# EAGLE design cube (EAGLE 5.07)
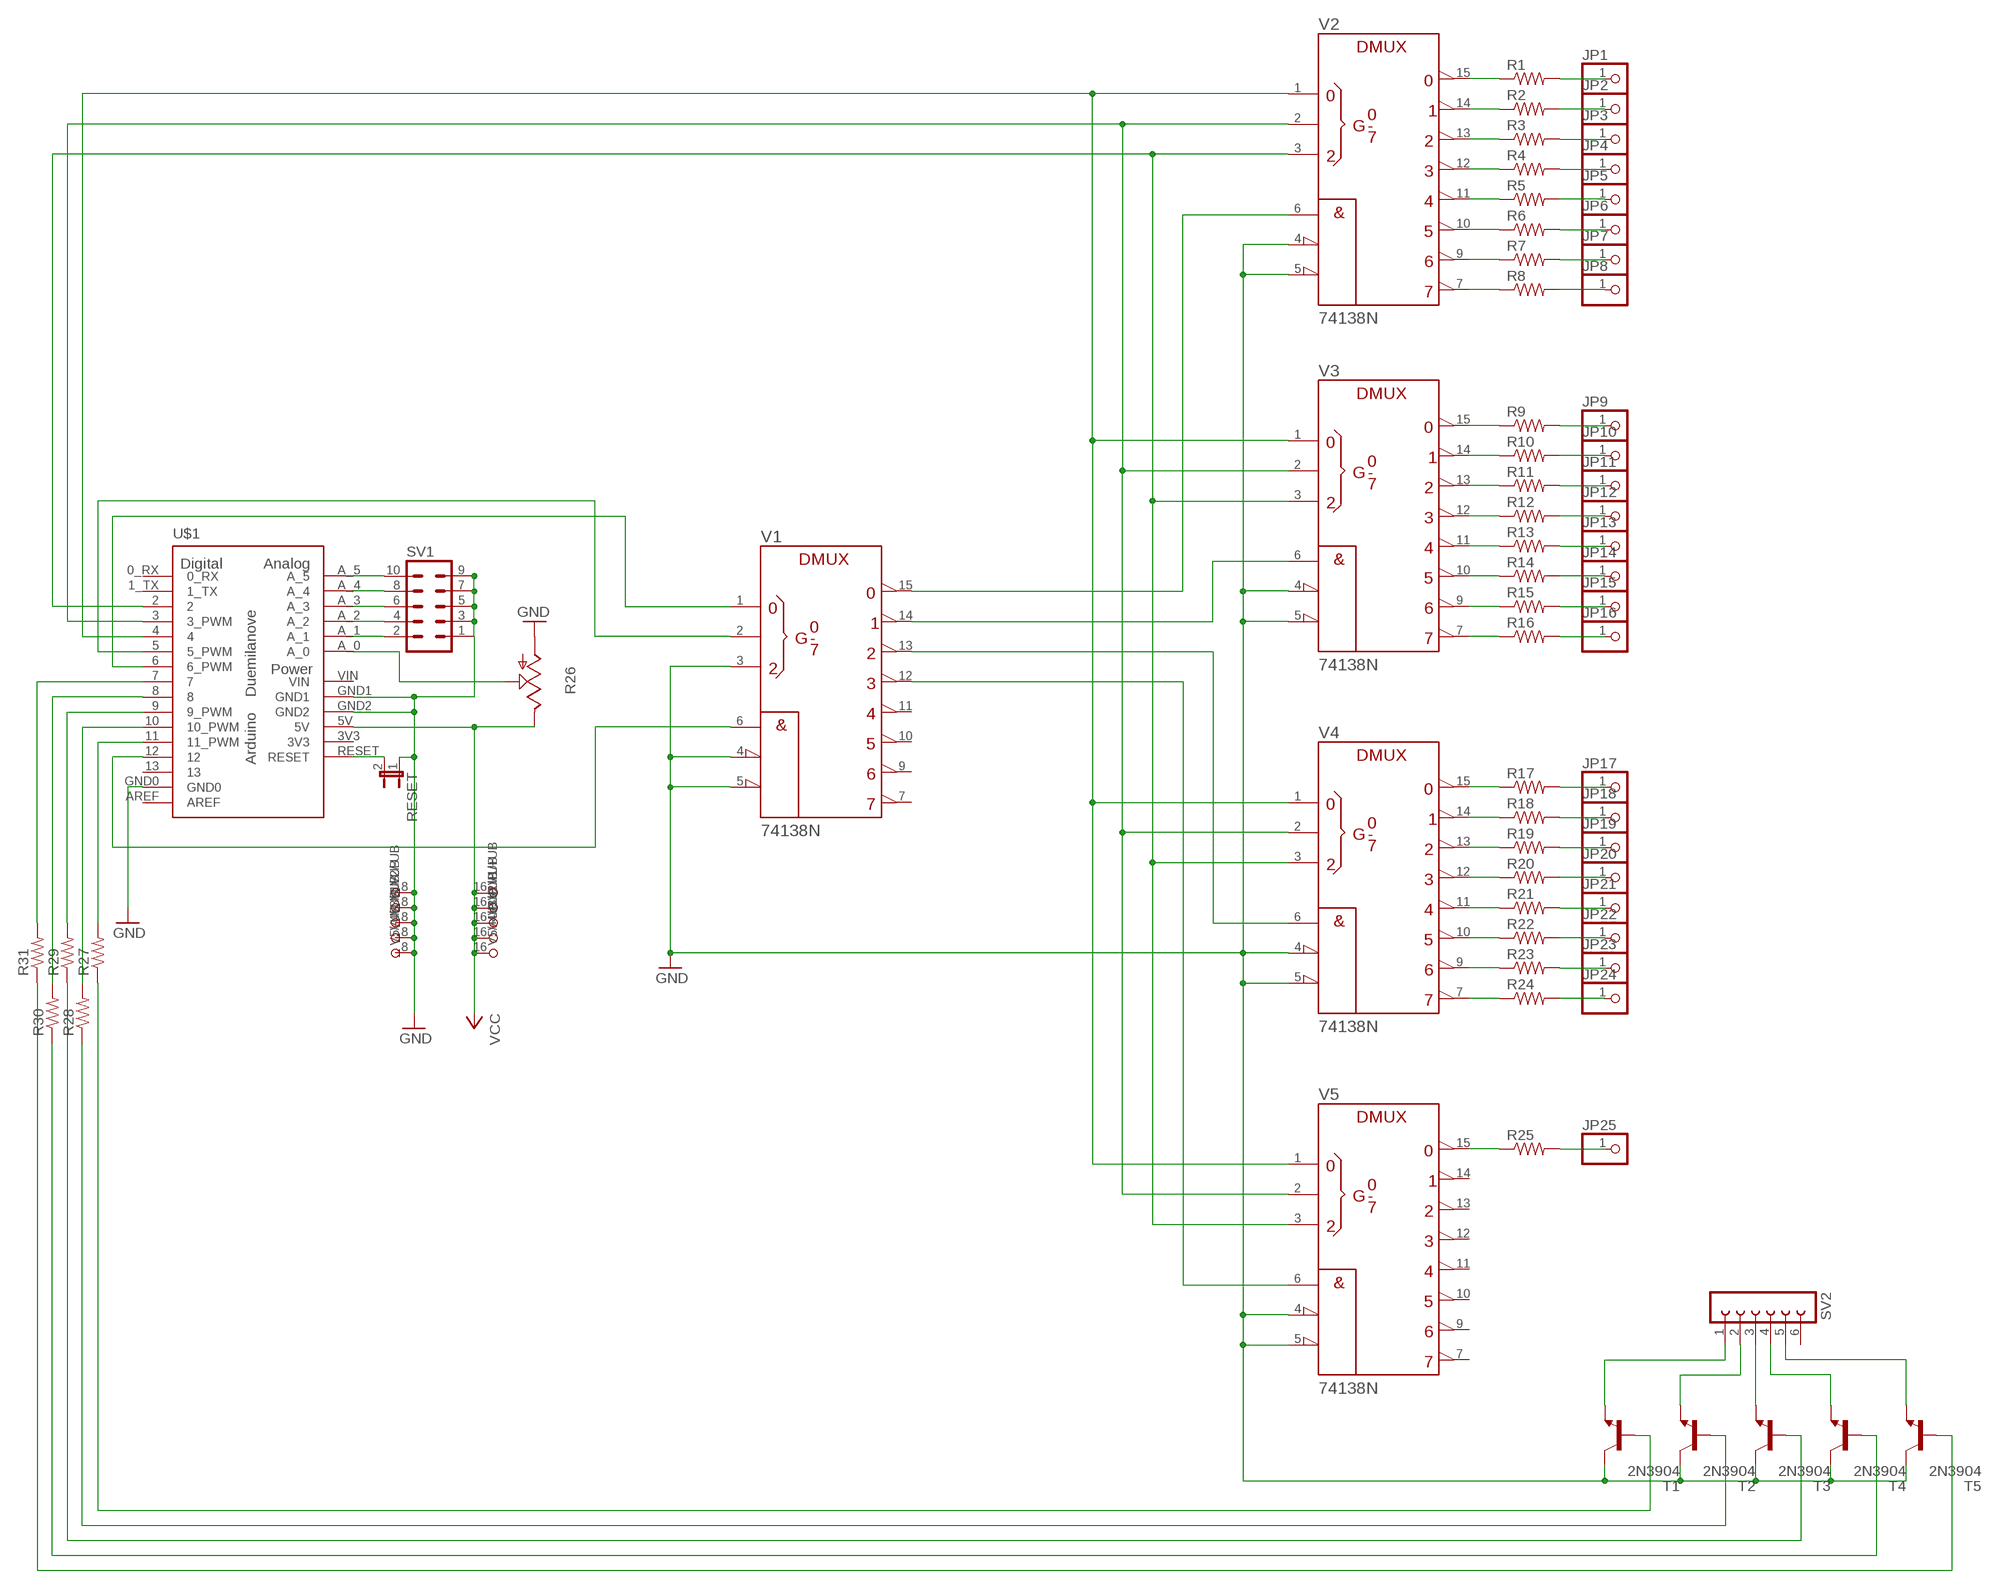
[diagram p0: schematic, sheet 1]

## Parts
JP1  PINHD-1X1  [1X01]
JP2  PINHD-1X1  [1X01]
JP3  PINHD-1X1  [1X01]
JP4  PINHD-1X1  [1X01]
JP5  PINHD-1X1  [1X01]
JP6  PINHD-1X1  [1X01]
JP7  PINHD-1X1  [1X01]
JP8  PINHD-1X1  [1X01]
JP9  PINHD-1X1  [1X01]
JP10  PINHD-1X1  [1X01]
JP11  PINHD-1X1  [1X01]
JP12  PINHD-1X1  [1X01]
JP13  PINHD-1X1  [1X01]
JP14  PINHD-1X1  [1X01]
JP15  PINHD-1X1  [1X01]
JP16  PINHD-1X1  [1X01]
JP17  PINHD-1X1  [1X01]
JP18  PINHD-1X1  [1X01]
JP19  PINHD-1X1  [1X01]
JP20  PINHD-1X1  [1X01]
JP21  PINHD-1X1  [1X01]
JP22  PINHD-1X1  [1X01]
JP23  PINHD-1X1  [1X01]
JP24  PINHD-1X1  [1X01]
JP25  PINHD-1X1  [1X01]
R1  R-US_0207/10  [0207/10]
R2  R-US_0207/10  [0207/10]
R3  R-US_0207/10  [0207/10]
R4  R-US_0207/10  [0207/10]
R5  R-US_0207/10  [0207/10]
R6  R-US_0207/10  [0207/10]
R7  R-US_0207/10  [0207/10]
R8  R-US_0207/10  [0207/10]
R9  R-US_0207/10  [0207/10]
R10  R-US_0207/10  [0207/10]
R11  R-US_0207/10  [0207/10]
R12  R-US_0207/10  [0207/10]
R13  R-US_0207/10  [0207/10]
R14  R-US_0207/10  [0207/10]
R15  R-US_0207/10  [0207/10]
R16  R-US_0207/10  [0207/10]
R17  R-US_0207/10  [0207/10]
R18  R-US_0207/10  [0207/10]
R19  R-US_0207/10  [0207/10]
R20  R-US_0207/10  [0207/10]
R21  R-US_0207/10  [0207/10]
R22  R-US_0207/10  [0207/10]
R23  R-US_0207/10  [0207/10]
R24  R-US_0207/10  [0207/10]
R25  R-US_0207/10  [0207/10]
R26  TRIM_US-CA6V  [CA6V]
R27  R-US_0207/10  [0207/10]
R28  R-US_0207/10  [0207/10]
R29  R-US_0207/10  [0207/10]
R30  R-US_0207/10  [0207/10]
R31  R-US_0207/10  [0207/10]
RESET  JP1E  [JP1]
SV1  MA05-2  [MA05-2]
SV2  FE06-1  [FE06]
T1  2N3904  [TO92]
T2  2N3904  [TO92]
T3  2N3904  [TO92]
T4  2N3904  [TO92]
T5  2N3904  [TO92]
U$1  ARDUINO-USBOCTAGONAL_PADS  [SHIELD-OCTAGONALPAD]
V1  74138N  [DIL16]
V2  74138N  [DIL16]
V3  74138N  [DIL16]
V4  74138N  [DIL16]
V5  74138N  [DIL16]

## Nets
GND: R26.A RESET.1 SV1.1 SV1.3 SV1.5 SV1.7 SV1.9 T1.1(C) T2.1(C) T3.1(C) T4.1(C) T5.1(C) U$1.GND0 U$1.GND1 U$1.GND2 V1.3(C) V1.4(!G2A) V1.5(!G2B) V1.8(-UB) V2.4(!G2A) V2.5(!G2B) V2.8(-UB) V3.4(!G2A) V3.5(!G2B) V3.8(-UB) V4.4(!G2A) V4.5(!G2B) V4.8(-UB) V5.4(!G2A) V5.5(!G2B) V5.8(-UB)
N$1: U$1.6(6_PWM) V1.1(A)
N$2: U$1.12 V1.6(G1)
N$3: V1.15(Y0) V2.6(G1)
N$4: V1.14(Y1) V3.6(G1)
N$5: V1.13(Y2) V4.6(G1)
N$6: V1.12(Y3) V5.6(G1)
N$7: U$1.4 V2.1(A) V3.1(A) V4.1(A) V5.1(A)
N$8: U$1.3(3_PWM) V2.2(B) V3.2(B) V4.2(B) V5.2(B)
N$9: U$1.2 V2.3(C) V3.3(C) V4.3(C) V5.3(C)
N$10: R27.1 T1.2(B)
N$11: R28.1 T2.2(B)
N$12: R29.1 T3.2(B)
N$13: R30.1 T4.2(B)
N$14: R31.1 T5.2(B)
N$15: R1.1 V2.15(Y0)
N$16: R2.1 V2.14(Y1)
N$17: R3.1 V2.13(Y2)
N$18: R4.1 V2.12(Y3)
N$19: R5.1 V2.11(Y4)
N$20: R6.1 V2.10(Y5)
N$21: R7.1 V2.9(Y6)
N$22: R8.1 V2.7(Y7)
N$23: R9.1 V3.15(Y0)
N$24: R10.1 V3.14(Y1)
N$25: R11.1 V3.13(Y2)
N$26: R12.1 V3.12(Y3)
N$27: R13.1 V3.11(Y4)
N$28: R14.1 V3.10(Y5)
N$29: R15.1 V3.9(Y6)
N$30: R16.1 V3.7(Y7)
N$31: R17.1 V4.15(Y0)
N$32: R18.1 V4.14(Y1)
N$33: R19.1 V4.13(Y2)
N$34: R20.1 V4.12(Y3)
N$35: R21.1 V4.11(Y4)
N$36: R22.1 V4.10(Y5)
N$37: R23.1 V4.9(Y6)
N$38: R24.1 V4.7(Y7)
N$39: R25.1 V5.15(Y0)
N$40: JP1.1 R1.2
N$41: JP2.1 R2.2
N$42: JP3.1 R3.2
N$43: JP4.1 R4.2
N$44: JP5.1 R5.2
N$45: JP6.1 R6.2
N$46: JP7.1 R7.2
N$47: JP8.1 R8.2
N$48: JP9.1 R9.2
N$49: JP10.1 R10.2
N$50: JP11.1 R11.2
N$51: JP12.1 R12.2
N$52: JP13.1 R13.2
N$53: JP14.1 R14.2
N$54: JP15.1 R15.2
N$55: JP16.1 R16.2
N$56: JP17.1 R17.2
N$57: JP18.1 R18.2
N$58: JP19.1 R19.2
N$59: JP20.1 R20.2
N$60: JP21.1 R21.2
N$61: JP22.1 R22.2
N$62: JP23.1 R23.2
N$63: JP24.1 R24.2
N$64: JP25.1 R25.2
N$65: SV2.1 T1.3(E)
N$66: SV2.2 T2.3(E)
N$67: SV2.3 T3.3(E)
N$68: SV2.4 T4.3(E)
N$69: SV2.5 T5.3(E)
N$70: U$1.5(5_PWM) V1.2(B)
N$71: SV1.2 U$1.A_1
N$72: SV1.4 U$1.A_2
N$73: SV1.6 U$1.A_3
N$74: SV1.8 U$1.A_4
N$75: SV1.10 U$1.A_5
N$76: R26.S U$1.A_0
N$77: R27.2 U$1.11(11_PWM)
N$78: RESET.2 U$1.RESET
N$79: R28.2 U$1.10(10_PWM)
N$80: R29.2 U$1.9(9_PWM)
N$81: R30.2 U$1.8
N$82: R31.2 U$1.7
VCC: R26.E U$1.5V V1.16(+UB) V2.16(+UB) V3.16(+UB) V4.16(+UB) V5.16(+UB)
Unconnected: SV2.6 U$1.0_RX U$1.1_TX U$1.13 U$1.AREF V1.7(Y7) V1.9(Y6) V1.10(Y5) V1.11(Y4) V5.7(Y7) V5.9(Y6) V5.10(Y5) V5.11(Y4) V5.12(Y3) V5.13(Y2) V5.14(Y1)

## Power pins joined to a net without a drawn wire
3V3: U$1.3V3
VIN: U$1.VIN

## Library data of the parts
JP1-JP25 = pinhead:PINHD-1X1: PIN HEADER
R1-R25 R27-R31 = rcl:R-US_: RESISTOR, American symbol
R26 = pot:TRIM_US-: POTENTIOMETER
RESET = jumper:JP1E: JUMPER
SV1 = con-lstb:MA05-2: PIN HEADER
SV2 = con-lsta:FE06-1: FEMALE HEADER
T1-T5 = transistor:2N3904: NPN TRANSISTOR
U$1 = Arduino-Various:ARDUINO-USB: The Ardiuno Duemilanove Pinouts layoutet as a Bare Shield. v0.5 Also for Arduino Diecimila. This is designed as a Part and has no Outline in the Dimension Layer. The Outline, when present, is drawed at the tPlace / bPlace Layer. Library by Stephanie Lange, http://www.k-ita.de/~sl/
V1-V5 = 74ttl-din:74*138: 3-line to 8-line DECODER/DEMULTIPLEXER

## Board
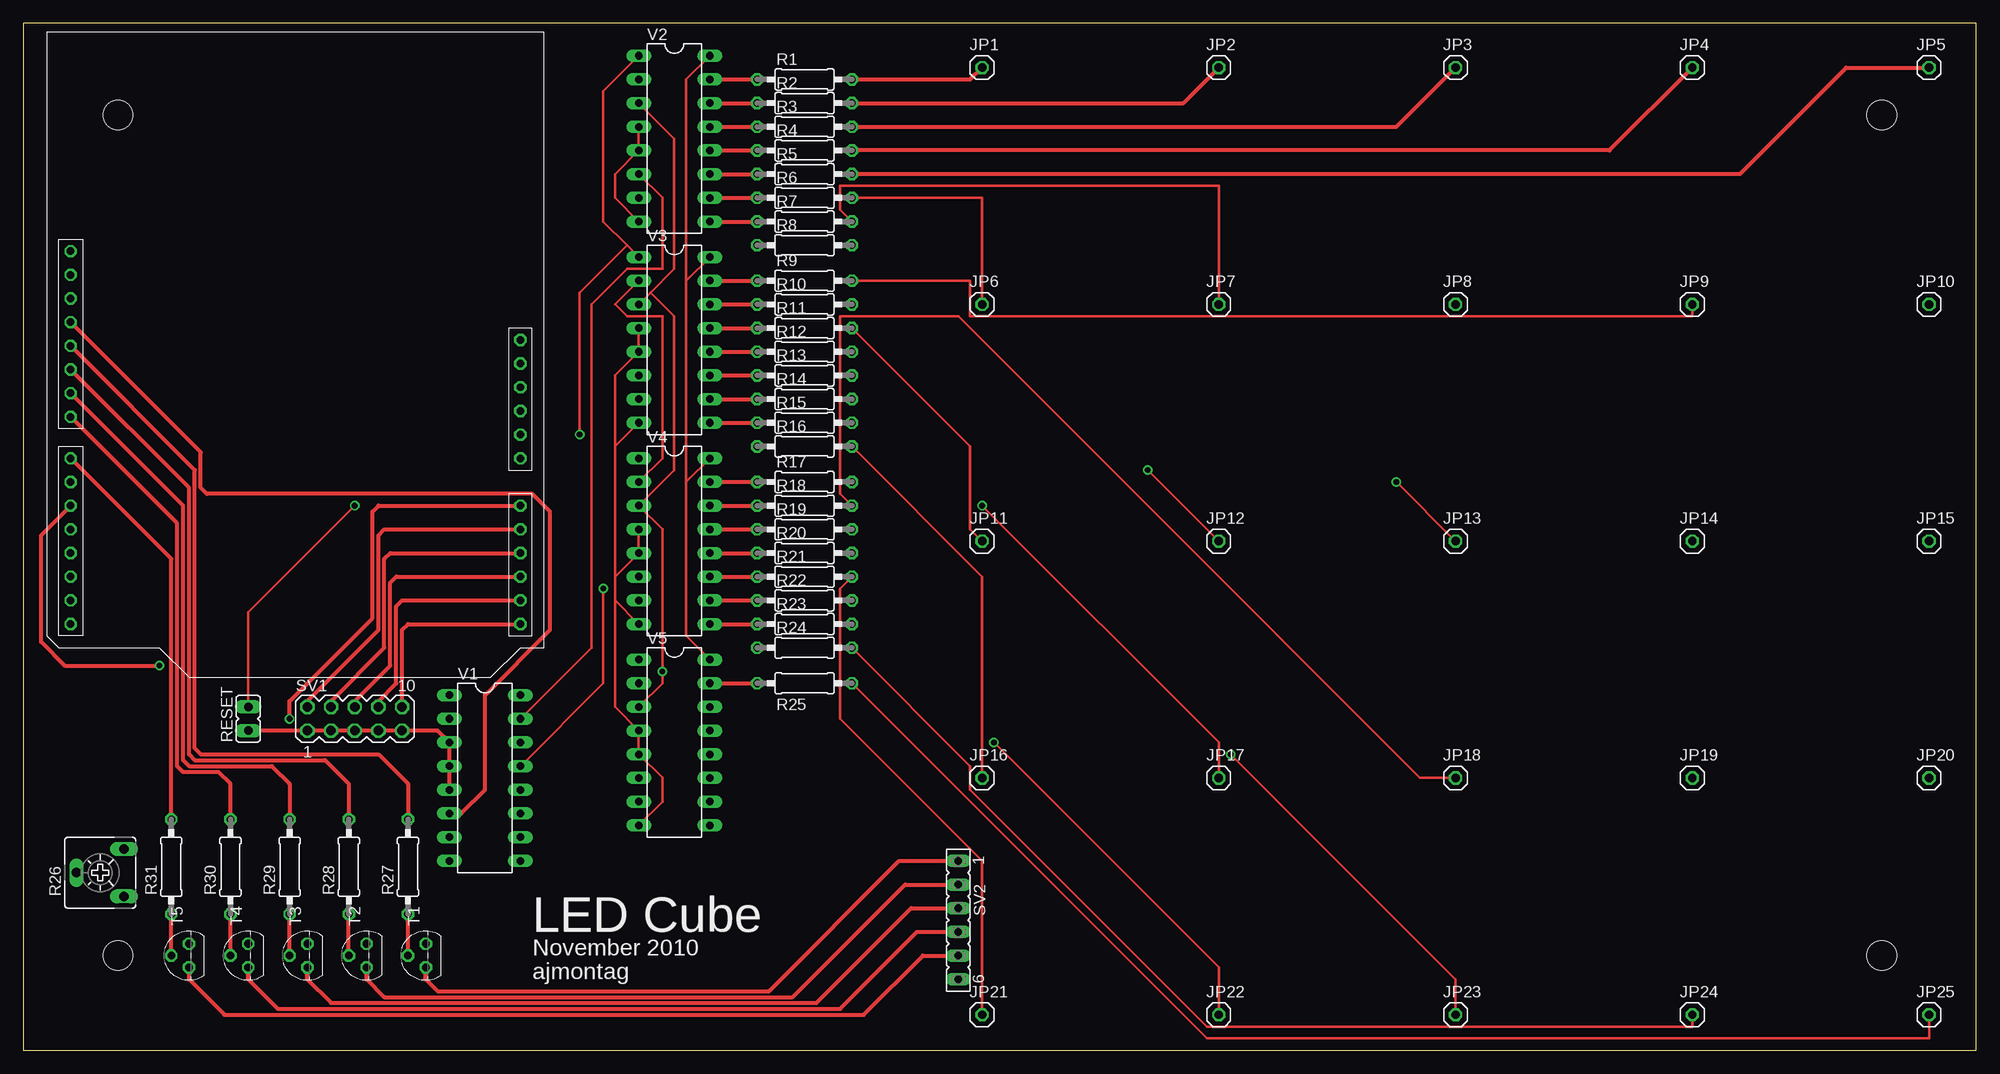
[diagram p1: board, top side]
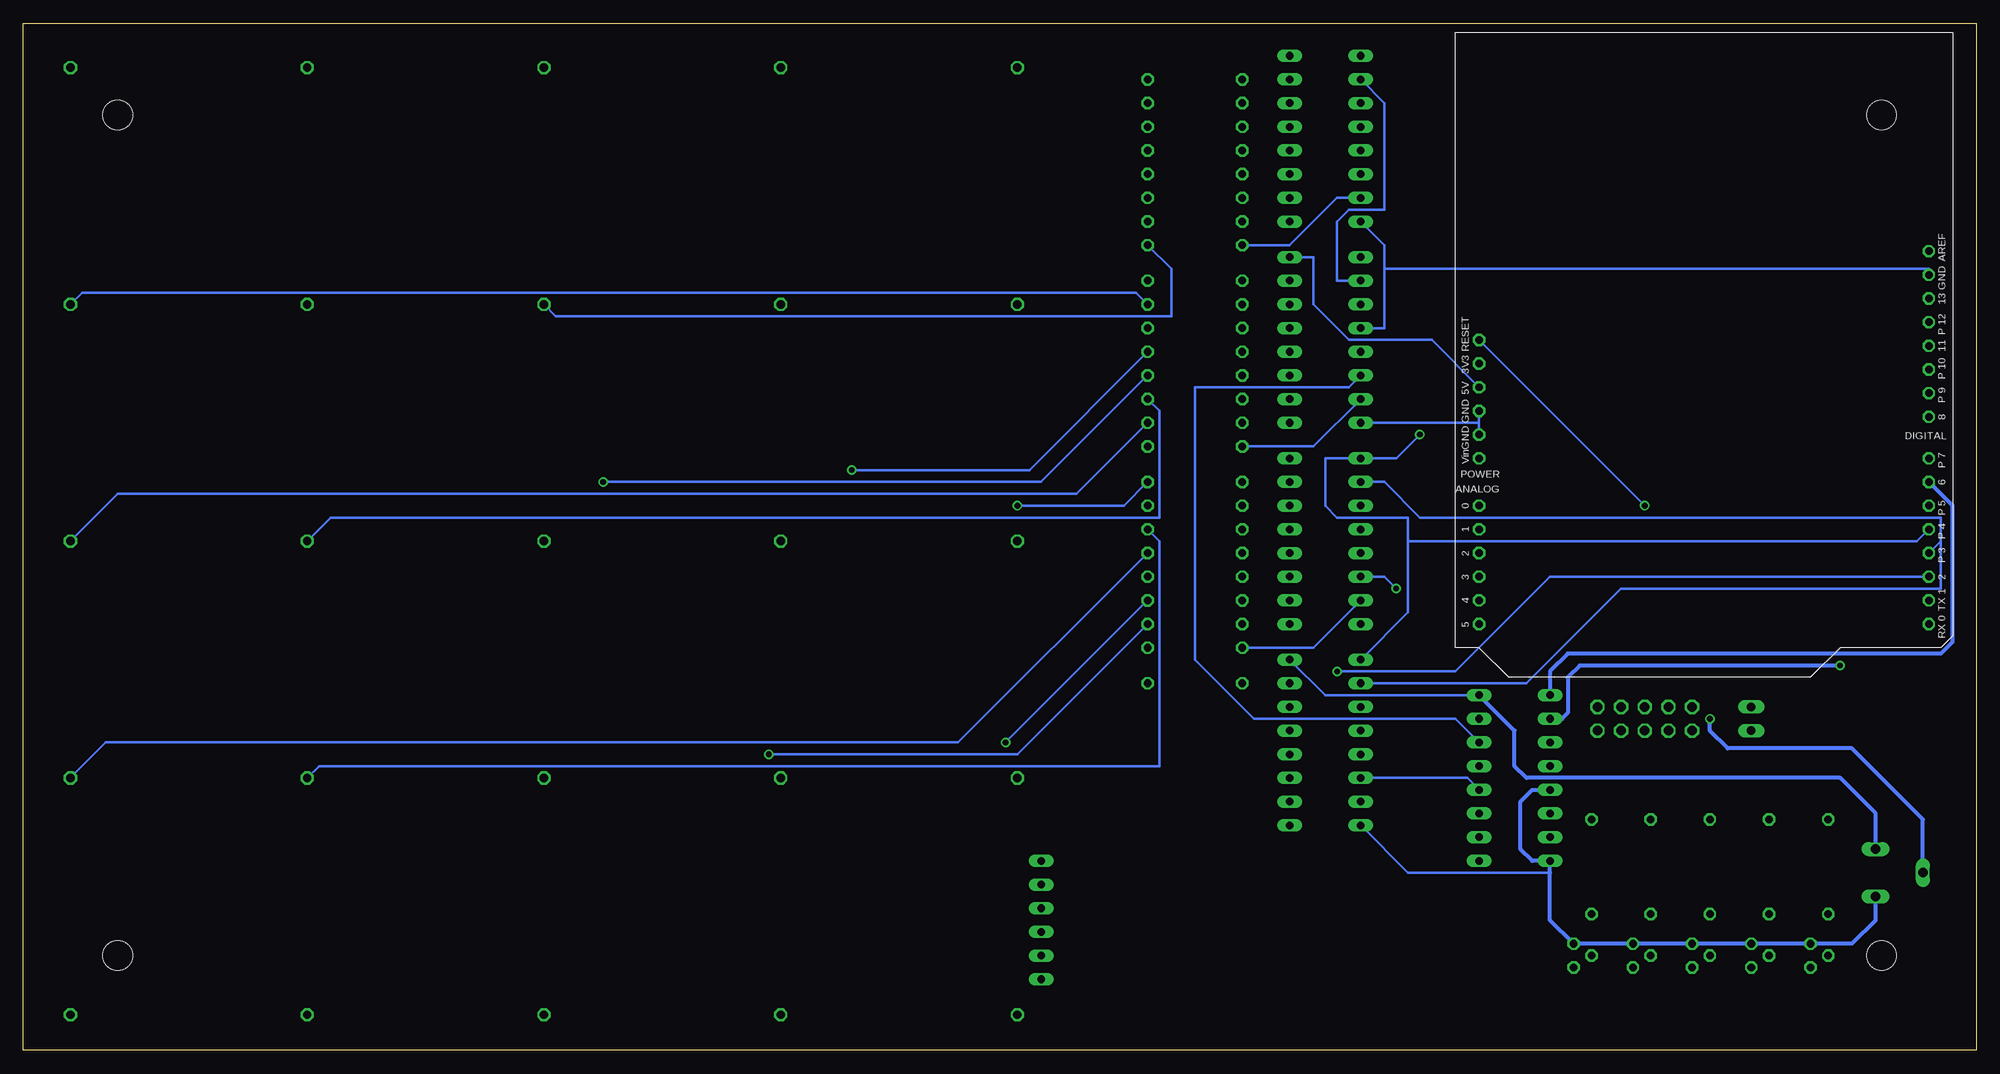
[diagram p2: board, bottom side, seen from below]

Size 209.53 x 110.16 mm. Coordinates in mm from the lower left corner, seen from the top.
Outline: 0,0 209.53,0 209.53,110.16 0,110.16 0,0
Copper layers (1*16): Top 0.035mm / dielectric 1.5mm / Bottom 0.035mm
Design rules "default": minimum track width 10mil, minimum drill 24mil, track to track 8mil, track to pad 8mil, pad to pad 8mil, via to via 8mil, smd to smd 8mil, copper to edge 40mil, drill to drill 8mil, minimum pad ring 10mil, minimum via ring 8mil, stop-mask expansion 4mil, vias tented up to drill 0mil, thermal gap 10mil
Holes 3.2 mm at 199.39,100.33 199.39,10.16 10.16,10.16 10.16,100.33

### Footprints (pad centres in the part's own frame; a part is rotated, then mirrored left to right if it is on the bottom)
1X01 = drill 0.9 octagon: 1 0,0
0207/10 = drill 0.813 octagon: 1 -5.08,0; 2 5.08,0
CA6V = drill 1.016 long: A -2.54,-2.54; E 2.54,-2.54; S 0,2.54
JP1 = drill 0.914 long: 1 0,-1.27; 2 0,1.27
MA05-2 = drill 1.016 octagon: 1 -5.08,-1.27; 2 -5.08,1.27; 3 -2.54,-1.27; 4 -2.54,1.27; 5 0,-1.27; 6 0,1.27; 7 2.54,-1.27; 8 2.54,1.27; 9 5.08,-1.27; 10 5.08,1.27
FE06 = drill 0.813 long: 1 -6.35,0; 2 -3.81,0; 3 -1.27,0; 4 1.27,0; 5 3.81,0; 6 6.35,0
TO92 = drill 0.813 octagon: 1 1.27,0; 2 0,1.905; 3 -1.27,0
SHIELD-OCTAGONALPAD = drill 0.8 pad 1.27 octagon: 0_RX -25.4,27.94; 1_TX -25.4,25.4; 2 -25.4,22.86; 3 -25.4,20.32; 3V3 22.86,0; 4 -25.4,17.78; 5 -25.4,15.24; 5V 22.86,2.54; 6 -25.4,12.7; 7 -25.4,10.16; 8 -25.4,5.715; 9 -25.4,3.175; 10 -25.4,0.635; 11 -25.4,-1.905; 12 -25.4,-4.445; 13 -25.4,-6.985; A_0 22.86,15.24; A_1 22.86,17.78; A_2 22.86,20.32; A_3 22.86,22.86; A_4 22.86,25.4; A_5 22.86,27.94; AREF -25.4,-12.065; GND0 -25.4,-9.525; GND1 22.86,7.62; GND2 22.86,5.08; RESET 22.86,-2.54; VIN 22.86,10.16
DIL16 = drill 0.813 long: 1 -8.89,-3.81; 2 -6.35,-3.81; 3 -3.81,-3.81; 4 -1.27,-3.81; 5 1.27,-3.81; 6 3.81,-3.81; 7 6.35,-3.81; 8 8.89,-3.81; 9 8.89,3.81; 10 6.35,3.81; 11 3.81,3.81; 12 1.27,3.81; 13 -1.27,3.81; 14 -3.81,3.81; 15 -6.35,3.81; 16 -8.89,3.81

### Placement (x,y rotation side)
JP1  102.87,105.41 0 top
JP2  128.27,105.41 0 top
JP3  153.67,105.41 0 top
JP4  179.07,105.41 0 top
JP5  204.47,105.41 0 top
JP6  102.87,80.01 0 top
JP7  128.27,80.01 0 top
JP8  153.67,80.01 0 top
JP9  179.07,80.01 0 top
JP10  204.47,80.01 0 top
JP11  102.87,54.61 0 top
JP12  128.27,54.61 0 top
JP13  153.67,54.61 0 top
JP14  179.07,54.61 0 top
JP15  204.47,54.61 0 top
JP16  102.87,29.21 0 top
JP17  128.27,29.21 0 top
JP18  153.67,29.21 0 top
JP19  179.07,29.21 0 top
JP20  204.47,29.21 0 top
JP21  102.87,3.81 0 top
JP22  128.27,3.81 0 top
JP23  153.67,3.81 0 top
JP24  179.07,3.81 0 top
JP25  204.47,3.81 0 top
R1  83.82,104.14 0 top
R2  83.82,101.6 0 top
R3  83.82,99.06 0 top
R4  83.82,96.52 0 top
R5  83.82,93.98 0 top
R6  83.82,91.44 0 top
R7  83.82,88.9 0 top
R8  83.82,86.36 0 top
R9  83.82,82.55 0 top
R10  83.82,80.01 0 top
R11  83.82,77.47 0 top
R12  83.82,74.93 0 top
R13  83.82,72.39 0 top
R14  83.82,69.85 0 top
R15  83.82,67.31 0 top
R16  83.82,64.77 0 top
R17  83.82,60.96 0 top
R18  83.82,58.42 0 top
R19  83.82,55.88 0 top
R20  83.82,53.34 0 top
R21  83.82,50.8 0 top
R22  83.82,48.26 0 top
R23  83.82,45.72 0 top
R24  83.82,43.18 0 top
R25  83.82,39.37 0 top
R26  8.26,19.05 90 top
R27  41.27,19.69 90 top
R28  34.92,19.69 90 top
R29  28.57,19.69 90 top
R30  22.23,19.69 90 top
R31  15.88,19.69 90 top
RESET  24.13,35.56 0 top
SV1  35.56,35.56 0 top
SV2  100.33,13.97 270 top
T1  43.18,10.16 90 top
T2  36.83,10.16 90 top
T3  30.48,10.16 90 top
T4  24.13,10.16 90 top
T5  17.78,10.16 90 top
U$1  30.48,73.66 180 bottom
V1  49.53,29.21 270 top
V2  69.85,97.79 270 top
V3  69.85,76.2 270 top
V4  69.85,54.61 270 top
V5  69.85,33.02 270 top

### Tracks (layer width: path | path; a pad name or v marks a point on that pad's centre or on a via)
GND
  Top 0.254: V2.4 V2.5 63.5,93.98 63.5,91.44 V2.8 | V3.4 V3.5 63.5,72.39 63.5,64.77 | 63.5,48.26 V4.8 | 63.5,48.26 63.5,50.8 | 63.5,50.8 V4.5 V4.4 | 63.5,64.77 V3.8 | 63.5,50.8 63.5,64.77 | 63.5,48.26 63.5,36.83 V5.4 V5.5 68.58,29.21 68.58,26.67 V5.8
  Top 0.406: V1.5 V1.4 V1.3 44.45,34.29 SV1.9 SV1.7 SV1.5 SV1.3 SV1.1 RESET.1
  Bottom 0.254: 53.34,67.31 U$1.GND1 | 53.34,67.31 U$1.GND2 | V5.8 60.96,19.05 45.72,19.05 | V2.8 63.5,86.36 63.5,83.82 | 63.5,83.82 63.5,77.47 V3.4 | V3.8 53.34,67.31 | 63.5,83.82 5.08,83.82 U$1.GND0
  Bottom 0.406: V1.5 47.62,27.94 48.9,26.67 48.9,21.59 47.62,20.32 V1.8 45.72,19.05 45.72,13.97 T1.1 T2.1 T3.1 T4.1 T5.1 13.34,11.43 10.79,13.97 R26.A
N$1
  Bottom 0.406: V1.1 45.72,40.64 43.81,42.55 3.81,42.55 2.54,43.81 2.54,58.42 U$1.6
N$2
  Top 0.406: V1.6 46.99,25.4 49.53,27.94 49.53,38.1 56.52,45.08 56.52,57.78 54.61,59.69 19.68,59.69 19.05,60.33 19.05,64.14 U$1.12
N$3
  Top 0.254: V1.15 60.96,43.18 60.96,80.01 64.77,83.82 68.58,83.82 68.58,91.44 V2.6
N$4
  Bottom 0.254: V1.14 55.88,35.56 77.47,35.56 83.82,41.91 83.82,71.12 67.31,71.12 V3.6
N$5  (via drill 0.61)
  Top 0.254: V1.13 62.23,39.37 v62.23,49.53
  Bottom 0.254: v62.23,49.53 63.5,50.8 V4.6
N$6
  Bottom 0.254: V1.12 54.61,29.21 V5.6
N$7  (via drill 0.61)
  Top 0.254: 64.77,86.36 62.23,88.9 62.23,102.87 V2.1 | 64.77,86.36 V3.1 | 64.77,86.36 59.69,81.28 v59.69,66.04
  Bottom 0.254: V5.1 60.96,46.99 60.96,54.61 | 60.96,54.61 60.96,57.15 68.58,57.15 69.85,58.42 69.85,63.5 V4.1 62.23,63.5 v59.69,66.04 | U$1.4 6.35,54.61 60.96,54.61
N$8
  Top 0.254: V3.2 63.5,80.01 64.77,78.74 68.58,78.74 68.58,63.5 V4.2
  Bottom 0.254: V2.2 63.5,101.6 63.5,90.17 67.31,90.17 68.58,88.9 68.58,82.55 V3.2 | 3.81,54.61 U$1.3 | 3.81,54.61 3.81,57.15 59.69,57.15 63.5,60.96 V4.2 | V5.2 48.26,39.37 38.1,49.53 3.81,49.53 3.81,54.61
N$9  (via drill 0.61)
  Top 0.254: 67.31,81.28 69.85,83.82 69.85,97.79 V2.3 | 67.31,81.28 V3.3 | V5.3 68.58,39.37 v68.58,40.64 68.58,55.88 V4.3 69.85,62.23 69.85,78.74 67.31,81.28
  Bottom 0.254: U$1.2 45.72,50.8 55.88,40.64 v68.58,40.64
N$10
  Top 0.406: T1.2 R27.1
N$11
  Top 0.406: T2.2 R28.1
N$12
  Top 0.406: T3.2 R29.1
N$13
  Top 0.406: T4.2 R30.1
N$14
  Top 0.406: T5.2 R31.1
N$15
  Top 0.406: V2.15 R1.1
N$16
  Top 0.406: V2.14 R2.1
N$17
  Top 0.406: V2.13 R3.1
N$18
  Top 0.406: V2.12 R4.1
N$19
  Top 0.406: V2.11 R5.1
N$20
  Top 0.406: V2.10 R6.1
N$21
  Top 0.406: V2.9 R7.1
N$22
  Bottom 0.254: V2.7 68.58,91.44 73.66,86.36 R8.1
N$23
  Top 0.406: V3.15 R9.1
N$24
  Top 0.406: V3.14 R10.1
N$25
  Top 0.406: V3.13 R11.1
N$26
  Top 0.406: V3.12 R12.1
N$27
  Top 0.406: V3.11 R13.1
N$28
  Top 0.406: V3.10 R14.1
N$29
  Top 0.406: V3.9 R15.1
N$30
  Bottom 0.254: V3.7 71.12,64.77 R16.1
N$31
  Top 0.406: V4.15 R17.1
N$32
  Top 0.406: V4.14 R18.1
N$33
  Top 0.406: V4.13 R19.1
N$34
  Top 0.406: V4.12 R20.1
N$35
  Top 0.406: V4.11 R21.1
N$36
  Top 0.406: V4.10 R22.1
N$37
  Top 0.406: V4.9 R23.1
N$38
  Bottom 0.254: V4.7 71.12,43.18 R24.1
N$39
  Top 0.406: V5.15 R25.1
N$40
  Top 0.406: R1.2 101.6,104.14 JP1.1
N$41
  Top 0.406: R2.2 124.46,101.6 JP2.1
N$42
  Top 0.406: R3.2 147.32,99.06 JP3.1
N$43
  Top 0.406: R4.2 170.18,96.52 JP4.1
N$44
  Top 0.406: R5.2 184.15,93.98 195.58,105.41 JP5.1
N$45
  Top 0.254: R6.2 102.87,91.44 JP6.1
N$46
  Top 0.254: R7.2 87.63,90.17 87.63,92.71 128.27,92.71 JP7.1
N$47
  Bottom 0.254: R8.2 86.36,83.82 86.36,78.74 152.4,78.74 JP8.1
N$48
  Top 0.254: R9.2 101.6,82.55 101.6,78.74 179.07,78.74 JP9.1
N$49
  Bottom 0.254: R10.2 90.17,81.28 203.2,81.28 JP10.1
N$50
  Top 0.254: R11.2 101.6,64.77 101.6,55.88 JP11.1
N$51  (via drill 0.61)
  Top 0.254: v120.65,62.23 JP12.1
  Bottom 0.254: R12.2 101.6,62.23 v120.65,62.23
N$52  (via drill 0.61)
  Top 0.254: v147.32,60.96 JP13.1
  Bottom 0.254: R13.2 100.33,60.96 v147.32,60.96
N$53
  Bottom 0.254: R14.2 87.63,68.58 87.63,57.15 176.53,57.15 JP14.1
N$54
  Bottom 0.254: R15.2 96.52,59.69 199.39,59.69 JP15.1
N$55
  Top 0.254: R16.2 102.87,50.8 JP16.1
N$56  (via drill 0.61 pad 1.02)
  Top 0.254: v102.87,58.42 128.27,33.02 JP17.1
  Bottom 0.254: R17.2 91.44,58.42 v102.87,58.42
N$57
  Top 0.254: R18.2 87.63,59.69 87.63,78.74 100.33,78.74 149.86,29.21 JP18.1
N$58
  Bottom 0.254: R19.2 87.63,54.61 87.63,30.48 177.8,30.48 JP19.1
N$59
  Bottom 0.254: R20.2 109.22,33.02 200.66,33.02 JP20.1
N$60
  Top 0.254: R21.2 87.63,49.53 87.63,35.56 102.87,20.32 JP21.1
N$61  (via drill 0.61 pad 1.02)
  Top 0.254: v104.14,33.02 128.27,8.89 JP22.1
  Bottom 0.254: v104.14,33.02 R22.2
N$62  (via drill 0.61 pad 1.02)
  Top 0.254: v129.54,31.75 153.67,7.62 JP23.1
  Bottom 0.254: R23.2 102.87,31.75 v129.54,31.75
N$63
  Top 0.254: R24.2 101.6,30.48 101.6,27.94 127,2.54 179.07,2.54 JP24.1
N$64
  Top 0.254: R25.2 127,1.27 204.47,1.27 JP25.1
N$65
  Top 0.406: T1.3 43.18,7.62 44.45,6.35 80.01,6.35 93.98,20.32 SV2.1
N$66
  Top 0.406: T2.3 36.83,7.62 38.73,5.71 82.55,5.71 94.61,17.78 SV2.2
N$67
  Top 0.406: T3.3 30.48,7.62 33.02,5.08 85.09,5.08 95.25,15.24 SV2.3
N$68
  Top 0.406: T4.3 24.13,7.62 27.3,4.45 87.63,4.45 95.89,12.7 SV2.4
N$69
  Top 0.406: T5.3 17.78,7.62 21.59,3.81 90.17,3.81 96.52,10.16 SV2.5
N$70  (via drill 0.61)
  Top 0.406: v14.61,41.27 4.45,41.27 1.91,43.81 1.91,55.25 U$1.5
  Bottom 0.406: V1.2 44.45,35.56 43.81,36.2 43.81,40 42.55,41.27 v14.61,41.27
N$71
  Top 0.406: SV1.2 30.48,37.47 38.1,45.08 38.1,55.25 38.73,55.88 U$1.A_1
N$72
  Top 0.406: SV1.4 33.02,37.47 38.73,43.18 38.73,52.7 39.37,53.34 U$1.A_2
N$73
  Top 0.406: SV1.6 35.56,37.47 39.37,41.27 39.37,50.17 40.01,50.8 U$1.A_3
N$74
  Top 0.406: SV1.8 38.1,37.47 40.01,39.37 40.01,47.62 40.64,48.26 U$1.A_4
N$75
  Top 0.406: SV1.10 40.64,45.08 41.27,45.72 U$1.A_5
N$76  (via drill 0.61)
  Top 0.406: v28.57,35.56 28.57,37.47 37.47,46.36 37.47,57.78 38.1,58.42 U$1.A_0
  Bottom 0.406: R26.S 5.71,24.77 13.34,32.39 26.67,32.39 28.57,34.29 v28.57,35.56
N$77
  Top 0.406: R27.2 41.27,28.57 38.1,31.75 19.05,31.75 18.41,32.39 18.41,62.23 U$1.11
N$78  (via drill 0.61 pad 1.02)
  Top 0.254: v35.56,58.42 24.13,46.99 RESET.2
  Bottom 0.254: v35.56,58.42 U$1.RESET
N$79
  Top 0.406: R28.2 34.92,28.57 32.38,31.11 18.41,31.11 17.78,31.75 17.78,60.33 U$1.10
N$80
  Top 0.406: R29.2 28.57,28.57 26.67,30.48 17.78,30.48 17.14,31.11 17.14,58.42 U$1.9
N$81
  Top 0.406: R30.2 22.23,28.57 20.95,29.84 17.14,29.84 16.51,30.48 16.51,56.52 U$1.8
N$82
  Top 0.406: R31.2 15.88,52.7 U$1.7
VCC
  Top 0.254: 71.12,60.96 V4.16 | 71.12,60.96 71.12,44.45 V5.16 | 71.12,82.55 V3.16 | 71.12,60.96 71.12,82.55 | V2.16 71.12,104.14 71.12,82.55
  Bottom 0.254: V1.16 69.85,38.1 V5.16 | U$1.5V 58.42,76.2 67.31,76.2 71.12,80.01 71.12,85.09 V3.16
  Bottom 0.406: R26.E 10.79,25.4 14.61,29.21 48.26,29.21 49.53,30.48 49.53,34.29 V1.16

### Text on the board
tPlace: LED Cube | November 2010 | ajmontag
